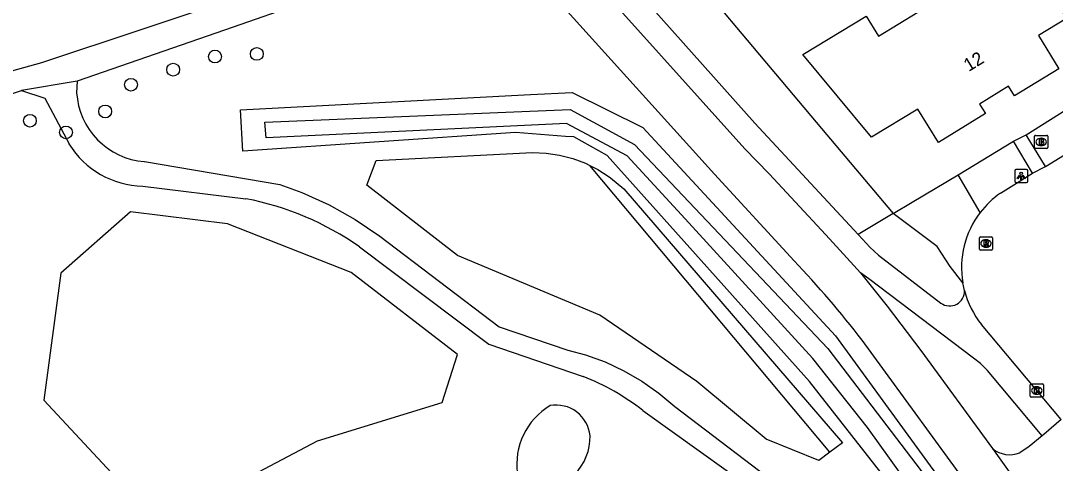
# Model space of a CAD drawing. Extents: x 157321 to 158827, y 386650 to 388532.
# Drawn here: x 157836.9 to 157916.1, y 387151.9 to 387185.7 of the extents above; entities that cross this region are included whole.
import ezdxf

# ---------------------------------------------------------------- set-up
doc = ezdxf.new("R2010")
doc.units = 0
for name, color, linetype in [('IMGEO_Boom', 7, 'Continuous'), ('IMGEO_Brandkraan', 7, 'Continuous'), ('IMGEO_Fietspad_gesloten', 7, 'Continuous'), ('IMGEO_Groenvoorziening', 7, 'Continuous'), ('IMGEO_Kolk', 7, 'Continuous'), ('IMGEO_Lichtpunt', 7, 'Continuous'), ('IMGEO_Meer_plas_ven_vijver', 7, 'Continuous'), ('IMGEO_Pand', 7, 'Continuous'), ('IMGEO_Pand_nummerreeks', 7, 'Continuous'), ('IMGEO_Rijbaan_lokaal_gesloten', 7, 'Continuous'), ('IMGEO_Rioolput', 7, 'Continuous'), ('IMGEO_Voetpad_halfverhard', 7, 'Continuous'), ('IMGEO_Voetpad_onverhard', 7, 'Continuous'), ('IMGEO_Voetpad_open', 7, 'Continuous'), ('IMGEO_Waterloop', 7, 'Continuous')]:
    doc.layers.add(name, color=color, linetype=linetype)

msp = doc.modelspace()

# ---------------------------------------------------------------- linework, layer by layer
at = {"layer": 'IMGEO_Boom'}
for centre in [(157851.77, 387183), (157854.97, 387183.2), (157848.57, 387182), (157845.342, 387180.843), (157843.37, 387178.8), (157837.613, 387178.092), (157840.37, 387177.2)]:
    msp.add_circle(centre, 0.489, dxfattribs=at)
at = {"layer": 'IMGEO_Brandkraan'}
for p, q in [((157914.475, 387176.048), (157914.475, 387176.9)), ((157914.55, 387176.974), (157915.402, 387176.974)), ((157914.963, 387176.754), (157914.988, 387176.754)), ((157915.476, 387176.9), (157915.476, 387176.048)), ((157915.402, 387175.974), (157914.55, 387175.974)), ((157914.986, 387176.194), (157914.961, 387176.194))]:
    msp.add_line(p, q, dxfattribs=at)
for points in [[(157914.475, 387176.048), (157914.475, 387176.9)], [(157914.55, 387176.974), (157915.402, 387176.974)], [(157914.823, 387176.674), (157914.823, 387176.274), (157915.036, 387176.274)], [(157915.054, 387176.674), (157914.823, 387176.674)], [(157915.476, 387176.9), (157915.476, 387176.048)], [(157915.402, 387175.974), (157914.55, 387175.974)], [(157915.002, 387176.593), (157914.948, 387176.593), (157914.948, 387176.517)], [(157914.948, 387176.517), (157915.001, 387176.517)], [(157915.01, 387176.441), (157914.948, 387176.441), (157914.948, 387176.36)], [(157914.948, 387176.36), (157915.01, 387176.36)]]:
    msp.add_lwpolyline(points, dxfattribs=at)
for centre, radius, start, end in [((157914.552, 387176.898), 0.0765, 91.55205, 178.44795), ((157914.552, 387176.898), 0.0765, 91.55205, 178.44795), ((157915.058, 387176.529), 0.145, 59.4692, 91.53667), ((157915.083, 387176.576), 0.0922, 285.51372, 58.15012), ((157915.4, 387176.898), 0.0765, 1.55205, 88.44795), ((157915.4, 387176.898), 0.0765, 1.55205, 88.44795), ((157914.552, 387176.05), 0.0765, 181.55205, 268.44795), ((157914.552, 387176.05), 0.0765, 181.55205, 268.44795), ((157915.003, 387176.555), 0.0379, 267.82845, 90.93552), ((157915.011, 387176.4), 0.0404, 269.87594, 90.50774), ((157915.042, 387176.525), 0.251, 268.66757, 293.53466), ((157915.088, 387176.384), 0.105, 301.31148, 78.98903), ((157915.4, 387176.05), 0.0765, 271.55205, 358.44795), ((157915.4, 387176.05), 0.0765, 271.55205, 358.44795)]:
    msp.add_arc(centre, radius, start, end, dxfattribs=at)
for centre, major_axis, ratio, start_param, end_param in [((157914.962, 387176.474), (-0.387, 0.002), 0.722429, 4.712389, 7.853982), ((157914.987, 387176.474), (-0.39, 0.002), 0.717154, 1.570796, 4.712389)]:
    msp.add_ellipse(centre, major_axis=major_axis, ratio=ratio, start_param=start_param, end_param=end_param, dxfattribs=at)
at = {"layer": 'IMGEO_Fietspad_gesloten'}
for points in [[(157878.581, 387191.399), (157879.562, 387190.147), (157892.311, 387175.938), (157894.159, 387174.032), (157898.507, 387169.378), (157900.653, 387167.019), (157901.149, 387166.477)], [(157896.068, 387167.393), (157889.992, 387174.02), (157877.294, 387188.065)], [(157901.149, 387166.477), (157903.193, 387163.928), (157905.762, 387160.526), (157911.252, 387153.028)], [(157910.286, 387148.989), (157901.292, 387161.32)], [(157916.496, 387155.264), (157915.169, 387154.121), (157915.044, 387154.017)], [(157915.044, 387154.017), (157914.047, 387153.19), (157913.34, 387152.705)], [(157911.252, 387153.028), (157915.39, 387147.25), (157915.414, 387147.249)]]:
    msp.add_lwpolyline(points, dxfattribs=at)
for centre, radius, start, end in [((157835.864, 387110.322), 82.956, 37.93465, 43.46965), ((157912.579, 387154.699), 2.134, 231.53485, 290.87798)]:
    msp.add_arc(centre, radius, start, end, dxfattribs=at)
at = {"layer": 'IMGEO_Groenvoorziening'}
for points in [[(157884.229, 387194.094), (157898.176, 387177.492), (157903.649, 387170.993)], [(157913.818, 387177.012), (157921.757, 387182.016)], [(157906.499, 387146.353), (157897.254, 387158.154), (157881.768, 387175.438), (157879.214, 387176.849), (157878.591, 387176.898), (157874.762, 387177.196), (157853.91, 387175.758), (157853.711, 387178.93), (157875.918, 387180.088), (157879.082, 387180.253), (157884.495, 387177.58), (157899.23, 387161.641), (157909.092, 387148.143), (157909.83, 387147.134), (157926.137, 387124.816), (157935.276, 387114.872), (157939.605, 387108.739), (157942.777, 387100.684), (157942.53, 387100.602), (157941.129, 387100.135), (157939.216, 387099.497), (157935.894, 387108.446), (157934.2, 387110.542), (157934.058, 387110.717)], [(157908.629, 387173.965), (157912.855, 387176.528)], [(157898.817, 387152.763), (157897.975, 387152.124), (157893.945, 387153.751), (157888.639, 387158.16), (157881.217, 387163.242), (157870.324, 387167.796), (157863.383, 387173.162), (157864.106, 387175.047), (157876.052, 387175.671), (157877.095, 387175.625), (157878.128, 387175.47), (157879.138, 387175.209), (157880.116, 387174.843), (157880.455, 387174.674)], [(157880.455, 387174.674), (157881.05, 387174.377), (157881.93, 387173.815), (157882.038, 387173.738), (157883.052, 387172.884), (157899.769, 387153.484), (157898.817, 387152.763)], [(157898.817, 387152.763), (157880.455, 387174.674)], [(157848.319, 387146.401), (157854.631, 387151.007), (157859.604, 387153.613), (157869.157, 387156.568), (157870.31, 387160.231), (157862.189, 387166.486), (157852.721, 387170.204), (157845.308, 387171.123), (157839.984, 387166.448), (157838.675, 387156.729), (157848.319, 387146.401)], [(157903.649, 387170.993), (157900.978, 387169.399)]]:
    msp.add_lwpolyline(points, dxfattribs=at)
at = {"layer": 'IMGEO_Kolk'}
for p, q in [((157914.14, 387157.045), (157914.14, 387157.897)), ((157914.215, 387157.971), (157915.067, 387157.971)), ((157914.628, 387157.751), (157914.653, 387157.751)), ((157915.141, 387157.897), (157915.141, 387157.045)), ((157915.067, 387156.971), (157914.215, 387156.971)), ((157914.651, 387157.191), (157914.626, 387157.191))]:
    msp.add_line(p, q, dxfattribs=at)
for points in [[(157914.14, 387157.045), (157914.14, 387157.897)], [(157914.215, 387157.971), (157915.067, 387157.971)], [(157914.461, 387157.671), (157914.584, 387157.671), (157914.584, 387157.52), (157914.714, 387157.671), (157914.878, 387157.671), (157914.732, 387157.52), (157914.885, 387157.271), (157914.733, 387157.271), (157914.648, 387157.435), (157914.584, 387157.368), (157914.584, 387157.271), (157914.461, 387157.271), (157914.461, 387157.671)], [(157915.141, 387157.897), (157915.141, 387157.045)], [(157915.067, 387156.971), (157914.215, 387156.971)]]:
    msp.add_lwpolyline(points, dxfattribs=at)
for centre, start, end in [((157914.217, 387157.895), 91.55205, 178.44795), ((157914.217, 387157.895), 91.55205, 178.44795), ((157915.065, 387157.895), 1.55205, 88.44795), ((157915.065, 387157.895), 1.55205, 88.44795), ((157914.217, 387157.047), 181.55205, 268.44795), ((157914.217, 387157.047), 181.55205, 268.44795), ((157915.065, 387157.047), 271.55205, 358.44795), ((157915.065, 387157.047), 271.55205, 358.44795)]:
    msp.add_arc(centre, 0.0765, start, end, dxfattribs=at)
for centre, major_axis, ratio, start_param, end_param in [((157914.627, 387157.471), (-0.387, 0.002), 0.722429, 4.712389, 7.853982), ((157914.652, 387157.471), (-0.39, 0.002), 0.717154, 1.570796, 4.712389)]:
    msp.add_ellipse(centre, major_axis=major_axis, ratio=ratio, start_param=start_param, end_param=end_param, dxfattribs=at)
at = {"layer": 'IMGEO_Lichtpunt'}
for p, q in [((157912.951, 387174.275), (157912.951, 387173.468)), ((157912.951, 387174.275), (157912.951, 387173.468)), ((157913.853, 387174.37), (157913.045, 387174.37)), ((157913.853, 387174.37), (157913.045, 387174.37)), ((157913.947, 387173.468), (157913.947, 387174.275)), ((157913.947, 387173.468), (157913.947, 387174.275)), ((157913.045, 387173.374), (157913.853, 387173.374)), ((157913.045, 387173.374), (157913.853, 387173.374))]:
    msp.add_line(p, q, dxfattribs=at)
for points in [[(157913.325, 387173.939), (157913.364, 387173.911), (157913.176, 387173.649), (157913.138, 387173.676), (157913.325, 387173.939)], [(157913.427, 387173.891), (157913.474, 387173.891), (157913.474, 387173.569), (157913.427, 387173.569), (157913.427, 387173.891)], [(157913.537, 387173.911), (157913.575, 387173.938), (157913.762, 387173.676), (157913.723, 387173.648), (157913.537, 387173.911)]]:
    msp.add_lwpolyline(points, dxfattribs=at)
msp.add_circle((157913.45, 387174.073), 0.0994, dxfattribs=at)
for centre, start, end in [((157913.045, 387174.275), 90, 180), ((157913.045, 387174.275), 90, 180), ((157913.853, 387174.275), 0, 90), ((157913.853, 387174.275), 0, 90), ((157913.045, 387173.468), 180, 270), ((157913.045, 387173.468), 180, 270), ((157913.853, 387173.468), 270, 0), ((157913.853, 387173.468), 270, 360)]:
    msp.add_arc(centre, 0.0946, start, end, dxfattribs=at)
at = {"layer": 'IMGEO_Meer_plas_ven_vijver'}
for centre, radius, start, end in [((157880.063, 387151.836), 5.206, 120.66753, 188.00464), ((157877.875, 387153.756), 2.6, 5.82619, 100.35001), ((157876.517, 387153.902), 3.947, 266.3405, 1.71604)]:
    msp.add_arc(centre, radius, start, end, dxfattribs=at)
at = {"layer": 'IMGEO_Pand'}
msp.add_lwpolyline([(157916.321, 387182.063), (157912.933, 387179.992), (157912.485, 387180.726), (157910.267, 387179.37), (157910.715, 387178.636), (157907.114, 387176.434), (157905.546, 387178.967), (157902, 387176.841), (157896.732, 387183.142), (157901.589, 387186.09), (157902.529, 387184.558), (157908.555, 387188.257), (157901.477, 387199.899), (157906.507, 387202.953), (157916.901, 387185.903), (157914.775, 387184.614), (157916.321, 387182.063)], dxfattribs=at)
at = {"layer": 'IMGEO_Rijbaan_lokaal_gesloten'}
for points in [[(157915.313, 387174.602), (157923.309, 387179.506)], [(157914.319, 387174.088), (157915.313, 387174.602)], [(157911.864, 387172.558), (157914.319, 387174.088)], [(157909.104, 387165.124), (157908.98, 387165.708)], [(157916.496, 387155.264), (157910.415, 387162.518)]]:
    msp.add_lwpolyline(points, dxfattribs=at)
for centre, radius, start, end in [((157915.834, 387166.829), 6.97, 124.72419, 142.40028), ((157915.789, 387166.872), 6.908, 142.45522, 189.7032), ((157915.726, 387166.822), 6.836, 194.38583, 219.02534)]:
    msp.add_arc(centre, radius, start, end, dxfattribs=at)
at = {"layer": 'IMGEO_Rioolput'}
for p, q in [((157910.247, 387168.282), (157910.247, 387169.134)), ((157910.322, 387169.208), (157911.174, 387169.208)), ((157910.735, 387168.988), (157910.76, 387168.988)), ((157911.248, 387169.134), (157911.248, 387168.282)), ((157911.174, 387168.208), (157910.322, 387168.208)), ((157910.758, 387168.428), (157910.733, 387168.428))]:
    msp.add_line(p, q, dxfattribs=at)
for points in [[(157910.247, 387168.282), (157910.247, 387169.134)], [(157910.322, 387169.208), (157911.174, 387169.208)], [(157910.836, 387168.906), (157910.584, 387168.908), (157910.584, 387168.508)], [(157910.762, 387168.827), (157910.708, 387168.827), (157910.708, 387168.746)], [(157910.708, 387168.746), (157910.76, 387168.746)], [(157911.248, 387169.134), (157911.248, 387168.282)], [(157911.174, 387168.208), (157910.322, 387168.208)], [(157910.584, 387168.508), (157910.708, 387168.508), (157910.708, 387168.67), (157910.719, 387168.67)], [(157910.766, 387168.641), (157910.837, 387168.508), (157910.977, 387168.508), (157910.912, 387168.634)]]:
    msp.add_lwpolyline(points, dxfattribs=at)
for centre, radius, start, end in [((157910.324, 387169.132), 0.0765, 91.55205, 178.44795), ((157910.324, 387169.132), 0.0765, 91.55205, 178.44795), ((157910.744, 387168.935), 0.19, 274.7715, 282.96867), ((157910.768, 387168.731), 0.0964, 77.00612, 93.18647), ((157910.782, 387168.788), 0.0378, 276.66336, 79.67722), ((157910.835, 387168.796), 0.109, 350.36119, 89.41601), ((157910.833, 387168.796), 0.112, 277.58423, 350.98172), ((157911.172, 387169.132), 0.0765, 1.55205, 88.44795), ((157911.172, 387169.132), 0.0765, 1.55205, 88.44795), ((157910.324, 387168.284), 0.0765, 181.55205, 268.44795), ((157910.324, 387168.284), 0.0765, 181.55205, 268.44795), ((157910.718, 387168.617), 0.0533, 26.02933, 88.69889), ((157910.817, 387168.581), 0.108, 29.51342, 73.79051), ((157911.172, 387168.284), 0.0765, 271.55205, 358.44795), ((157911.172, 387168.284), 0.0765, 271.55205, 358.44795)]:
    msp.add_arc(centre, radius, start, end, dxfattribs=at)
for centre, major_axis, ratio, start_param, end_param in [((157910.734, 387168.708), (-0.387, 0.002), 0.722429, 4.712389, 7.853982), ((157910.759, 387168.708), (-0.39, 0.002), 0.717154, 1.570796, 4.712389)]:
    msp.add_ellipse(centre, major_axis=major_axis, ratio=ratio, start_param=start_param, end_param=end_param, dxfattribs=at)
at = {"layer": 'IMGEO_Voetpad_halfverhard'}
for points in [[(157873.897, 387192.402), (157867.456, 387190.185), (157858.289, 387187.03), (157853.158, 387185.254), (157841.216, 387181.12)], [(157900.978, 387169.399), (157893.079, 387177.901), (157880.42, 387192.099)], [(157854.071, 387187.711), (157838.497, 387182.513), (157825.72, 387178.978)], [(157841.216, 387181.12), (157836.98, 387180.404)], [(157822.462, 387173.887), (157824.03, 387176.102), (157836.98, 387180.404)], [(157900.978, 387169.399), (157901.318, 387169.033), (157901.878, 387168.435), (157902.517, 387167.813), (157907.309, 387164.159)], [(157915.044, 387154.017), (157910.876, 387158.99), (157910.33, 387159.541), (157909.797, 387159.948), (157901.8, 387166.013), (157901.149, 387166.477)]]:
    msp.add_lwpolyline(points, dxfattribs=at)
msp.add_arc((157907.978, 387165.067), 1.128, 233.63578, 2.88957, dxfattribs=at)
at = {"layer": 'IMGEO_Voetpad_onverhard'}
for points in [[(157841.216, 387181.12), (157841.187, 387180.234), (157841.24, 387179.734), (157841.337, 387179.241), (157841.478, 387178.758), (157841.661, 387178.29), (157841.886, 387177.84), (157842.15, 387177.412), (157842.451, 387177.01), (157842.787, 387176.636), (157843.154, 387176.293), (157843.551, 387175.984), (157843.974, 387175.713), (157844.42, 387175.48), (157844.884, 387175.288), (157845.364, 387175.138), (157845.856, 387175.031), (157846.355, 387174.969), (157846.37, 387174.968), (157856.723, 387173.21), (157858.42, 387172.606), (157860.507, 387171.67), (157862.501, 387170.551), (157864.388, 387169.259), (157873.51, 387162.344), (157878.76, 387160.561), (157880.11, 387160.198), (157881.607, 387159.657), (157883.05, 387158.985), (157884.428, 387158.186), (157885.728, 387157.268), (157886.941, 387156.237), (157895.795, 387149.523)], [(157836.98, 387180.404), (157838.743, 387179.809), (157840.602, 387176.317)], [(157846.248, 387173.099), (157854.134, 387172.133)], [(157862.833, 387168.461), (157872.717, 387161.011), (157879.941, 387158.535)], [(157884.499, 387155.943), (157895.186, 387148.297), (157904.88, 387143.994)]]:
    msp.add_lwpolyline(points, dxfattribs=at)
for centre, radius, start, end in [((157846.36, 387179.858), 6.76, 211.58933, 269.04776), ((157849.767, 387149.647), 22.906, 55.22009, 79.00899), ((157873.589, 387142.061), 17.657, 51.83533, 68.91345)]:
    msp.add_arc(centre, radius, start, end, dxfattribs=at)
at = {"layer": 'IMGEO_Voetpad_open'}
for points in [[(157912.855, 387176.528), (157913.818, 387177.012)], [(157915.313, 387174.602), (157913.818, 387177.012)], [(157914.319, 387174.088), (157912.855, 387176.528)], [(157903.649, 387170.993), (157905.112, 387171.866), (157908.629, 387173.965)], [(157910.312, 387171.082), (157908.629, 387173.965)], [(157908.98, 387165.708), (157908.001, 387166.947), (157907.016, 387168.48), (157903.649, 387170.993)]]:
    msp.add_lwpolyline(points, dxfattribs=at)
at = {"layer": 'IMGEO_Waterloop'}
msp.add_lwpolyline([(157855.697, 387176.787), (157855.581, 387177.984), (157878.947, 387178.95), (157883.851, 387176.285), (157898.662, 387160.682), (157908.008, 387148.44), (157914.496, 387139.094), (157925.6, 387123.858), (157930.601, 387118.278), (157934.424, 387114.087), (157938.962, 387108.217), (157941.607, 387101.092), (157940.488, 387100.667), (157937.939, 387107.483), (157934.482, 387112.234), (157919.536, 387129.786), (157901.694, 387154.638), (157897.503, 387159.929), (157887.733, 387170.588), (157883.311, 387175.416), (157878.657, 387177.868), (157855.697, 387176.787)], dxfattribs=at)

# ---------------------------------------------------------------- texts
at = {"layer": 'IMGEO_Pand_nummerreeks'}
msp.add_text('12', height=1, rotation=31.43819, dxfattribs=at).set_placement((157909.431, 387181.813))

doc.saveas('drawing.dxf')
